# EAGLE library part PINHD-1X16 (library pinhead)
PIN HEADER
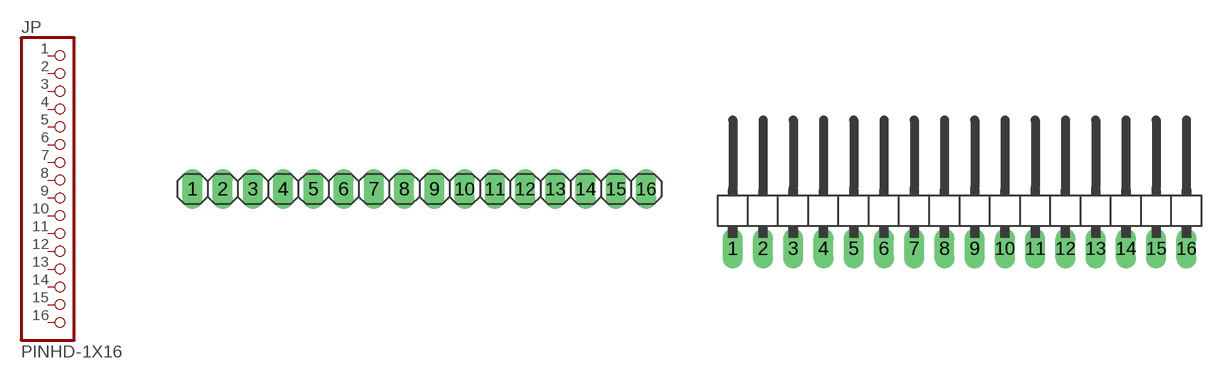
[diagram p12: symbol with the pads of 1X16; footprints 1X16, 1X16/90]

Designator prefix JP

## PINHD-1X16  [1X16]
1  1  pas
2  2  pas
3  3  pas
4  4  pas
5  5  pas
6  6  pas
7  7  pas
8  8  pas
9  9  pas
10  10  pas
11  11  pas
12  12  pas
13  13  pas
14  14  pas
15  15  pas
16  16  pas

## PINHD-1X16/90  [1X16/90]
Pads as for 1X16

## Footprint 1X16 (pad centres in mm)
PIN HEADER
drill 1.016 pad 1.67 long: 1 -19.05,0; 2 -16.51,0; 3 -13.97,0; 4 -11.43,0; 5 -8.89,0; 6 -6.35,0; 7 -3.81,0; 8 -1.27,0; 9 1.27,0; 10 3.81,0; 11 6.35,0; 12 8.89,0; 13 11.43,0; 14 13.97,0; 15 16.51,0; 16 19.05,0

## Footprint 1X16/90 (pad centres in mm)
PIN HEADER
drill 1.016 pad 1.67 long: 1 -19.05,-3.81; 2 -16.51,-3.81; 3 -13.97,-3.81; 4 -11.43,-3.81; 5 -8.89,-3.81; 6 -6.35,-3.81; 7 -3.81,-3.81; 8 -1.27,-3.81; 9 1.27,-3.81; 10 3.81,-3.81; 11 6.35,-3.81; 12 8.89,-3.81; 13 11.43,-3.81; 14 13.97,-3.81; 15 16.51,-3.81; 16 19.05,-3.81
